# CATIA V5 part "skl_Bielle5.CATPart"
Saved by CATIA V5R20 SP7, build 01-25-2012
Part number: skl_Bielle5
Publications: "Axe_Levier1Bielle5", "Axe_Bielle5Equerre7", "Point.1", "Point.2", "Plan.1", "Droite.4", "Droite.5", "Droite.6"
Bounding box of the stored display mesh (mm): x 0 to 20, y -10.033 to 0, z 123.588 to 152
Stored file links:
  J:\ACHTUNG2\skl_Bielle5.CATPart
  J:\cmilovidofIAO\skl_IAO.CATProduct
  J:\ACHTUNG2\skl_IAO2.CATProduct
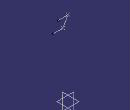
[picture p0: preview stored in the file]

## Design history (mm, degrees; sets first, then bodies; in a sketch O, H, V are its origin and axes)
Set1
  Point1: linked copy from another document
  Point2: linked copy from another document
  Plane1: linked copy from another document
Body1 (main body)
  Line1: type PtPt, FirstPoint Point1, SecondPoint Point2
  Line2: type Normal, RefPoint Point1, RefSkin Plane1, Start 0, End 20
  Line3: type Normal, RefPoint Point2, RefSkin Plane1, Start 0, End 20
